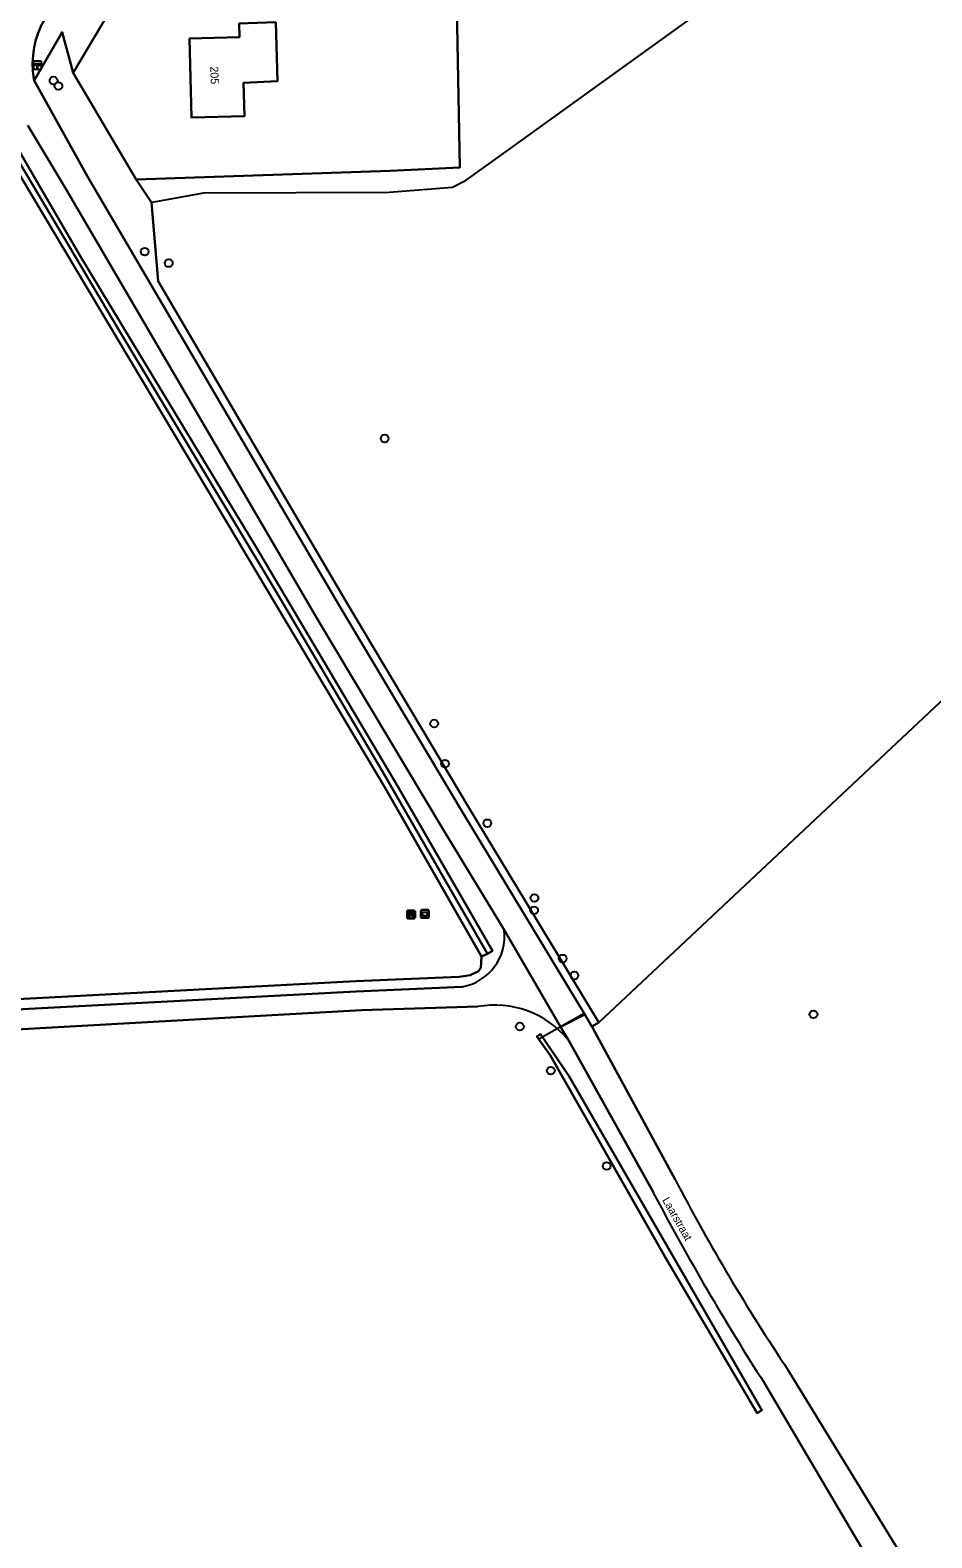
# Model space of a CAD drawing. Extents: x 160203 to 161530, y 379528 to 381797.
# Drawn here: x 160354.9 to 160468.3, y 379774.3 to 379963.9 of the extents above; entities that cross this region are included whole.
import ezdxf

# ---------------------------------------------------------------- set-up
doc = ezdxf.new("R2010")
doc.units = 0
for name, color, linetype in [('IMGEO_Afvalbak', 7, 'Continuous'), ('IMGEO_Bank', 7, 'Continuous'), ('IMGEO_Berm_groen', 7, 'Continuous'), ('IMGEO_Boom', 7, 'Continuous'), ('IMGEO_Erf', 7, 'Continuous'), ('IMGEO_Grasland_overig', 7, 'Continuous'), ('IMGEO_Groenvoorziening', 7, 'Continuous'), ('IMGEO_Hectometerpaal', 7, 'Continuous'), ('IMGEO_Hek', 7, 'Continuous'), ('IMGEO_Naaldbos', 7, 'Continuous'), ('IMGEO_Openbare_ruimte_label', 7, 'Continuous'), ('IMGEO_Pand', 7, 'Continuous'), ('IMGEO_Pand_nummerreeks', 7, 'Continuous'), ('IMGEO_Rijbaan_lokaal_gesloten', 7, 'Continuous'), ('IMGEO_Rijbaan_lokaal_halfverhard', 7, 'Continuous'), ('IMGEO_Waterloop', 7, 'Continuous')]:
    doc.layers.add(name, color=color, linetype=linetype)

msp = doc.modelspace()

# ---------------------------------------------------------------- linework, layer by layer
at = {"layer": 'IMGEO_Afvalbak'}
for p, q in [((160404.02, 379852.39), (160404.02, 379853.19)), ((160404.02, 379853.19), (160404.02, 379852.39)), ((160404.12, 379853.29), (160404.91, 379853.29)), ((160404.91, 379853.29), (160404.12, 379853.29)), ((160404.91, 379852.29), (160404.12, 379852.29)), ((160404.12, 379852.29), (160404.91, 379852.29)), ((160405.01, 379853.19), (160405.01, 379852.39)), ((160405.01, 379852.39), (160405.01, 379853.19))]:
    msp.add_line(p, q, dxfattribs=at)
msp.add_lwpolyline([(160404.16, 379853.01), (160404.87, 379853.01), (160404.72, 379852.54), (160404.31, 379852.54), (160404.16, 379853.01)], dxfattribs=at)
for centre, start, end in [((160404.12, 379853.19), 90, 180), ((160404.12, 379853.19), 90, 180), ((160404.12, 379852.39), 180, 270), ((160404.12, 379852.39), 180, 270), ((160404.91, 379853.19), 0, 90), ((160404.91, 379853.19), 360, 90), ((160404.91, 379852.39), 270, 0), ((160404.91, 379852.39), 270, 0)]:
    msp.add_arc(centre, 0.1, start, end, dxfattribs=at)
at = {"layer": 'IMGEO_Bank'}
for p, q in [((160402.29, 379852.29), (160402.29, 379853.13)), ((160402.29, 379853.13), (160402.29, 379852.29)), ((160402.36, 379853.22), (160403.2, 379853.22)), ((160403.2, 379853.22), (160402.36, 379853.22)), ((160403.21, 379852.22), (160402.37, 379852.22)), ((160402.37, 379852.22), (160403.21, 379852.22)), ((160402.98, 379852.62), (160402.59, 379852.62)), ((160402.6, 379852.72), (160402.6, 379852.83)), ((160402.64, 379852.83), (160402.64, 379852.72)), ((160402.93, 379852.84), (160402.65, 379852.84)), ((160402.65, 379852.72), (160402.93, 379852.72)), ((160402.94, 379852.72), (160402.94, 379852.83)), ((160402.98, 379852.83), (160402.98, 379852.72)), ((160403.29, 379853.14), (160403.29, 379852.3)), ((160403.29, 379852.3), (160403.29, 379853.14))]:
    msp.add_line(p, q, dxfattribs=at)
for points in [[(160402.54, 379852.62), (160402.39, 379852.62), (160402.5, 379852.72), (160402.59, 379852.72)], [(160402.59, 379852.84), (160402.5, 379852.84), (160402.5, 379853), (160403.07, 379853), (160403.07, 379852.84), (160402.99, 379852.84)], [(160402.59, 379852.61), (160402.59, 379852.4), (160402.54, 379852.4), (160402.54, 379852.61)], [(160402.99, 379852.72), (160403.07, 379852.72), (160403.18, 379852.62), (160403.04, 379852.62)], [(160403.03, 379852.61), (160403.03, 379852.4), (160402.99, 379852.4), (160402.99, 379852.61)]]:
    msp.add_lwpolyline(points, dxfattribs=at)
for centre, radius, start, end in [((160402.37, 379853.14), 0.0779, 92.4484, 184.2845), ((160402.37, 379853.14), 0.0779, 92.4484, 184.2845), ((160402.37, 379852.3), 0.0779, 182.4484, 274.2845), ((160402.37, 379852.3), 0.0779, 182.4484, 274.2845), ((160402.54, 379852.61), 0.00671, 2.8957, 87.1043), ((160402.59, 379852.83), 0.00671, 2.8957, 87.1043), ((160402.59, 379852.72), 0.00671, 272.8957, 357.1043), ((160402.59, 379852.61), 0.00671, 92.8957, 177.1043), ((160402.65, 379852.83), 0.00671, 92.8957, 177.1043), ((160402.65, 379852.72), 0.00671, 182.8957, 267.1043), ((160402.93, 379852.83), 0.00671, 2.8957, 87.1043), ((160402.93, 379852.72), 0.00671, 272.8957, 357.1043), ((160402.99, 379852.83), 0.00671, 92.8957, 177.1043), ((160402.99, 379852.72), 0.00671, 182.8957, 267.1043), ((160402.98, 379852.61), 0.00671, 2.8957, 87.1043), ((160403.04, 379852.61), 0.00671, 92.8957, 177.1043), ((160403.21, 379853.14), 0.0779, 2.4484, 94.2845), ((160403.21, 379853.14), 0.0779, 2.4484, 94.2845), ((160403.21, 379852.3), 0.0779, 272.4484, 4.2845), ((160403.21, 379852.3), 0.0779, 272.4484, 4.2845)]:
    msp.add_arc(centre, radius, start, end, dxfattribs=at)
at = {"layer": 'IMGEO_Berm_groen'}
msp.add_lwpolyline([(160375.89, 379997.42), (160357.91, 379967.3), (160356.34, 379964.6), (160355.94, 379963.68), (160355.63, 379962.74), (160355.41, 379961.77), (160355.27, 379960.79), (160355.22, 379959.8), (160355.26, 379958.81), (160355.39, 379957.82), (160355.43, 379957.61), (160358.93, 379963.68), (160360.33, 379958.58), (160382.33, 379995.65)], dxfattribs=at)
at = {"layer": 'IMGEO_Boom'}
for centre in [(160357.85, 379957.61), (160358.46, 379956.93), (160369.31, 379936.09), (160372.33, 379934.65), (160399.48, 379912.59), (160405.69, 379876.74), (160407.06, 379871.69), (160412.39, 379864.2), (160418.26, 379853.24), (160418.3, 379854.79), (160421.86, 379847.18), (160423.32, 379845.05), (160453.38, 379840.16), (160416.46, 379838.63), (160420.36, 379833.08), (160427.38, 379821.1)]:
    msp.add_circle(centre, 0.489, dxfattribs=at)
at = {"layer": 'IMGEO_Erf'}
for points in [[(160407.99, 379995.8), (160400.24, 379995.97), (160382.33, 379995.65), (160360.33, 379958.58), (160368.22, 379945.15), (160400.15, 379946.25), (160408.91, 379946.67)], [(160385.81, 379964.96), (160386.01, 379957.54), (160381.74, 379957.31), (160381.85, 379953.15), (160375.21, 379952.97), (160374.95, 379962.89), (160381.22, 379963.05), (160381.18, 379964.79)]]:
    msp.add_lwpolyline(points, close=True, dxfattribs=at)
at = {"layer": 'IMGEO_Grasland_overig'}
for points in [[(160407.99, 379995.8), (160408.91, 379946.67), (160400.15, 379946.25), (160368.22, 379945.15), (160370.16, 379942.26), (160371, 379932.38), (160383.71, 379910.71), (160394.58, 379892.15), (160410.1, 379866.11), (160426.4, 379839.14), (160576.07, 379979.7)], [(160796.26, 379769.76), (160808.14, 379784.24), (160814.61, 379791.79), (160576.07, 379979.7), (160426.4, 379839.14), (160425.52, 379838.65), (160425.54, 379838.62), (160425.7, 379838.36), (160435.98, 379819.4)], [(160352.45, 379947.67), (160378.38, 379904.17), (160399.59, 379868.58), (160411.66, 379847.42), (160412.38, 379847.79), (160399.2, 379870.72), (160385.68, 379893.58), (160366.11, 379926.16), (160352.83, 379948.55), (160349.84, 379948.27), (160289.95, 379848.06), (160290.49, 379847.67), (160330.19, 379914.23), (160350.12, 379947.64)], [(160411.2, 379841.14), (160396.58, 379840.7), (160323.24, 379836.57)], [(160433.25, 379817.74), (160422.53, 379836.98)], [(160450.12, 379795.52), (160467.63, 379766.93)], [(160472.68, 379750.63), (160447.21, 379793.79)]]:
    msp.add_lwpolyline(points, dxfattribs=at)
msp.add_lwpolyline([(160420.29, 379835.05), (160418.62, 379837.38), (160419.06, 379837.66), (160422.62, 379832.43), (160446.87, 379790.38), (160446.29, 379790.01), (160434.87, 379809.43)], close=True, dxfattribs=at)
for centre, radius, start, end in [((160413.33, 379829.44), 11.89, 39.3313, 100.3376), ((160663.33, 379937.86), 256.35, 207.5206, 213.7272), ((160714.26, 379965.55), 317.52, 207.7449, 212.7492)]:
    msp.add_arc(centre, radius, start, end, dxfattribs=at)
at = {"layer": 'IMGEO_Groenvoorziening'}
msp.add_lwpolyline([(160425.52, 379838.65), (160426.4, 379839.14), (160410.1, 379866.11), (160394.58, 379892.15), (160383.71, 379910.71), (160371, 379932.38), (160370.16, 379942.26), (160368.22, 379945.15), (160360.33, 379958.58), (160358.93, 379963.68), (160355.43, 379957.61), (160362.12, 379945.53), (160383.03, 379909.88), (160393.72, 379891.65), (160409.24, 379865.59), (160424.62, 379840.15)], close=True, dxfattribs=at)
for points in [[(160414.5, 379850.79), (160406.69, 379863.63), (160391.07, 379889.78), (160380.87, 379907.23), (160359.38, 379943.97), (160354.6, 379951.94)], [(160353.43, 379948.9), (160361.1, 379935.68), (160379.4, 379905.43), (160383.21, 379899.13), (160401.12, 379868.81), (160413.05, 379848.15), (160412.38, 379847.79), (160411.66, 379847.42), (160411.57, 379846), (160411.28, 379845.6), (160410.21, 379845.08), (160408.84, 379844.89), (160395.84, 379844.33), (160326.56, 379840.64)], [(160325.47, 379839.3), (160395.9, 379843.05), (160409.23, 379843.63)]]:
    msp.add_lwpolyline(points, dxfattribs=at)
msp.add_arc((160408.08, 379850), 6.47, 280.2664, 6.9736, dxfattribs=at)
at = {"layer": 'IMGEO_Hectometerpaal'}
for p, q in [((160355.33, 379959.95), (160355.33, 379959.11)), ((160355.33, 379959.95), (160355.33, 379959.11)), ((160356.24, 379960.04), (160355.4, 379960.04)), ((160356.24, 379960.04), (160355.4, 379960.04)), ((160356.33, 379959.12), (160356.33, 379959.96)), ((160356.33, 379959.12), (160356.33, 379959.96)), ((160355.41, 379959.04), (160356.25, 379959.04)), ((160355.41, 379959.04), (160356.25, 379959.04))]:
    msp.add_line(p, q, dxfattribs=at)
msp.add_lwpolyline([(160355.85, 379959.18), (160355.79, 379959.18), (160355.79, 379959.49), (160355.57, 379959.49), (160355.57, 379959.75), (160356.07, 379959.75), (160356.07, 379959.49), (160355.85, 379959.49), (160355.85, 379959.18)], dxfattribs=at)
for centre, start, end in [((160355.41, 379959.96), 92.4484, 184.2845), ((160355.41, 379959.96), 92.4484, 184.2845), ((160356.25, 379959.96), 2.4484, 94.2845), ((160356.25, 379959.96), 2.4484, 94.2845), ((160355.41, 379959.12), 182.4484, 274.2845), ((160355.41, 379959.12), 182.4484, 274.2845), ((160356.25, 379959.12), 272.4484, 4.2845), ((160356.25, 379959.12), 272.4484, 4.2845)]:
    msp.add_arc(centre, 0.0779, start, end, dxfattribs=at)
at = {"layer": 'IMGEO_Hek'}
for points in [[(160461.66, 379977.08), (160454.11, 379977.11), (160414.7, 379948.7)], [(160414.7, 379948.7), (160409.37, 379944.86), (160407.99, 379944.15), (160400.02, 379943.55), (160376.68, 379943.45), (160370.9, 379942.4), (160370.16, 379942.26)], [(160424.55, 379840.26), (160418.86, 379837.04)], [(160425.52, 379838.65), (160426.4, 379839.14)]]:
    msp.add_lwpolyline(points, dxfattribs=at)
at = {"layer": 'IMGEO_Naaldbos'}
msp.add_lwpolyline([(160350.12, 379947.64), (160330.19, 379914.23), (160290.49, 379847.67), (160289.95, 379848.06), (160289.38, 379848.46), (160285.52, 379842.88), (160285.39, 379842.42), (160285.36, 379841.67), (160285.4, 379841.12), (160285.57, 379840.56), (160286.32, 379839.16), (160293.26, 379839.13), (160321.57, 379840.37), (160326.56, 379840.64), (160395.84, 379844.33), (160408.84, 379844.89), (160410.21, 379845.08), (160411.28, 379845.6), (160411.57, 379846), (160411.66, 379847.42), (160399.59, 379868.58), (160378.38, 379904.17), (160352.45, 379947.67)], dxfattribs=at)
at = {"layer": 'IMGEO_Pand'}
msp.add_lwpolyline([(160385.81, 379964.96), (160381.18, 379964.79), (160381.22, 379963.05), (160374.95, 379962.89), (160375.21, 379952.97), (160381.85, 379953.15), (160381.74, 379957.31), (160386.01, 379957.54)], close=True, dxfattribs=at)
at = {"layer": 'IMGEO_Rijbaan_lokaal_gesloten'}
for points in [[(160354.6, 379951.94), (160359.38, 379943.97), (160380.87, 379907.23), (160391.07, 379889.78), (160406.69, 379863.63), (160414.5, 379850.79), (160421.59, 379838.6), (160424.62, 379840.15), (160409.24, 379865.59), (160393.72, 379891.65), (160383.03, 379909.88), (160362.12, 379945.53), (160355.43, 379957.61), (160355.39, 379957.82), (160355.26, 379958.81), (160355.22, 379959.8), (160355.27, 379960.79), (160355.41, 379961.77), (160355.63, 379962.74), (160355.94, 379963.68), (160356.34, 379964.6)], [(160435.98, 379819.4), (160425.7, 379838.36), (160425.54, 379838.62), (160425.52, 379838.65), (160424.62, 379840.15), (160421.59, 379838.6), (160422.53, 379836.98), (160433.25, 379817.74)], [(160447.21, 379793.79), (160472.68, 379750.63), (160477.11, 379744.07), (160482.04, 379736.75), (160484.53, 379735.46), (160486.15, 379736.46), (160487.06, 379737.02), (160484.53, 379741.3), (160480.94, 379746.53), (160478.64, 379750), (160470.83, 379761.7), (160467.63, 379766.93), (160450.12, 379795.52)]]:
    msp.add_lwpolyline(points, dxfattribs=at)
for centre, radius, start, end in [((160663.33, 379937.86), 256.35, 207.5206, 213.7272), ((160714.26, 379965.55), 317.52, 207.7449, 212.7492)]:
    msp.add_arc(centre, radius, start, end, dxfattribs=at)
at = {"layer": 'IMGEO_Rijbaan_lokaal_halfverhard'}
for points in [[(160422.53, 379836.98), (160421.59, 379838.6), (160414.5, 379850.79)], [(160409.23, 379843.63), (160395.9, 379843.05), (160325.47, 379839.3)], [(160323.24, 379836.57), (160396.58, 379840.7)], [(160396.58, 379840.7), (160411.2, 379841.14)]]:
    msp.add_lwpolyline(points, dxfattribs=at)
for centre, radius, start, end in [((160408.08, 379850), 6.47, 280.2664, 6.9736), ((160413.33, 379829.44), 11.89, 39.3313, 100.3376)]:
    msp.add_arc(centre, radius, start, end, dxfattribs=at)
at = {"layer": 'IMGEO_Waterloop'}
msp.add_lwpolyline([(160349.84, 379948.27), (160352.83, 379948.55), (160366.11, 379926.16), (160385.68, 379893.58), (160399.2, 379870.72), (160412.38, 379847.79), (160413.05, 379848.15), (160401.12, 379868.81), (160383.21, 379899.13), (160379.4, 379905.43), (160361.1, 379935.68), (160353.43, 379948.9)], dxfattribs=at)
msp.add_lwpolyline([(160422.62, 379832.43), (160419.06, 379837.66), (160418.62, 379837.38), (160420.29, 379835.05), (160434.87, 379809.43), (160446.29, 379790.01), (160446.87, 379790.38)], close=True, dxfattribs=at)

# ---------------------------------------------------------------- texts
at = {"layer": 'IMGEO_Openbare_ruimte_label'}
msp.add_text('Laarstraat', height=1, rotation=299.7165, dxfattribs=at).set_placement((160434.33, 379816.81))
at = {"layer": 'IMGEO_Pand_nummerreeks'}
msp.add_text('205', height=1, rotation=271.5009, dxfattribs=at).set_placement((160377.56, 379959.37))

doc.saveas('drawing.dxf')
